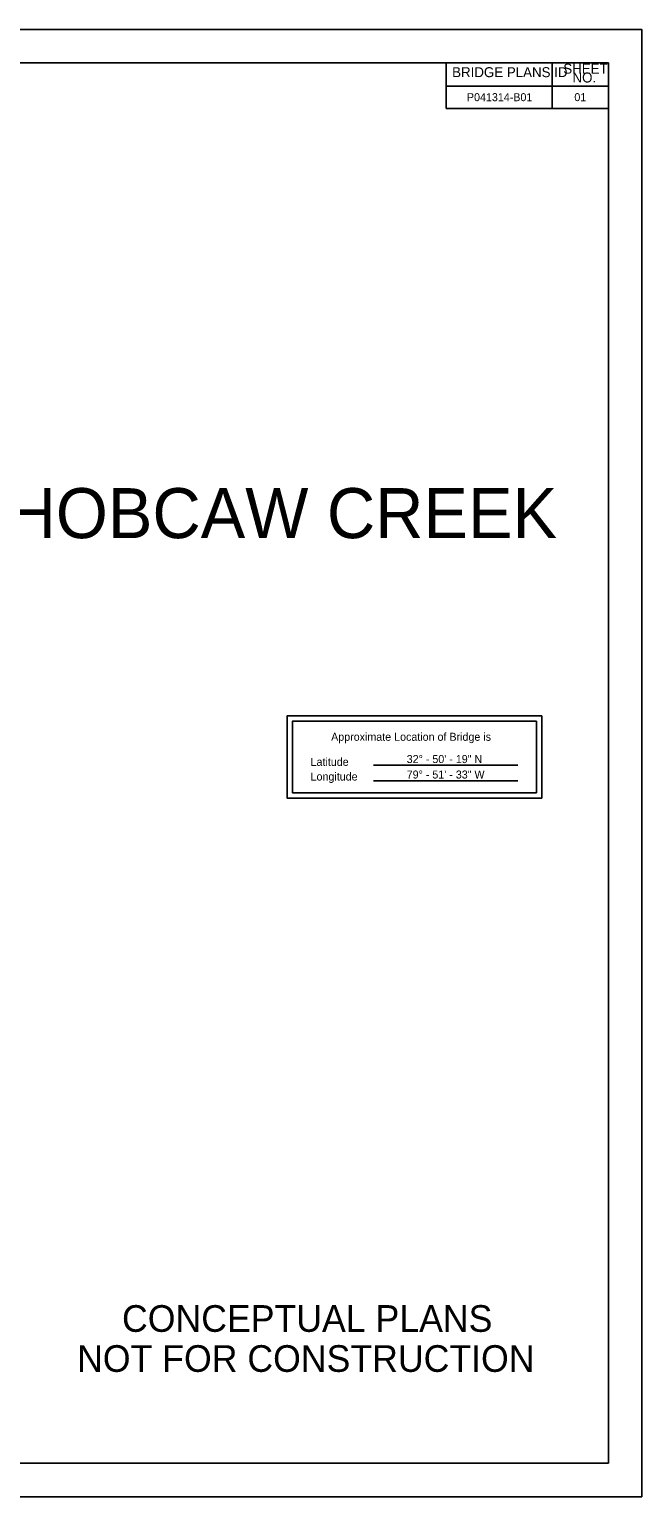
# Model space of a CAD drawing. Extents: x 291 to 2091, y 224 to 1324.
# Drawn here: x 1632 to 2091, y 224 to 1324 of the extents above; entities that cross this region are included whole.
import ezdxf

# ---------------------------------------------------------------- set-up
doc = ezdxf.new("R2010")
doc.units = 0
for name, color, linetype in [('BR_BORDER LINES', 7, 'Continuous'), ('BR_TEXT', 7, 'Continuous'), ('GN_TitleSheetMap', 7, 'Continuous'), ('RD_SHT_IplotShp', 7, 'Continuous')]:
    doc.layers.add(name, color=color, linetype=linetype)

msp = doc.modelspace()

# ---------------------------------------------------------------- linework, layer by layer
at = {"layer": 'BR_BORDER LINES'}
for p, q in [((391.1, 1299), (2066.1, 1299)), ((1944.4, 1299), (1944.4, 1264.8)), ((2023.9, 1264.8), (2023.9, 1299)), ((2066.1, 249.1), (2066.1, 1299)), ((1944.4, 1281.5), (2066.1, 1281.5)), ((2066.1, 1240.8), (2066.1, 1265.7)), ((1944.4, 1264.8), (2066.1, 1264.8)), ((2066.1, 888.4), (2066.1, 1240.8)), ((391.1, 249.1), (2066.1, 249.1))]:
    msp.add_line(p, q, dxfattribs=at)
at = {"layer": 'BR_TEXT'}
for points in [[(2016.1, 809.3), (1825, 809.3), (1825, 747.7), (2016.1, 747.7)], [(2012.1, 805.3), (1829, 805.3), (1829, 751.7), (2012.1, 751.7)]]:
    msp.add_lwpolyline(points, close=True, dxfattribs=at)
at = {"layer": 'GN_TitleSheetMap'}
for p, q in [((1890, 772.3), (1998.1, 772.3)), ((1890, 760.7), (1998.1, 760.7))]:
    msp.add_line(p, q, dxfattribs=at)
at = {"layer": 'RD_SHT_IplotShp'}
msp.add_lwpolyline([(291.1, 1324), (2091.1, 1324), (2091.1, 224), (291.1, 224)], close=True, dxfattribs=at)

# ---------------------------------------------------------------- texts
at = {"layer": 'BR_TEXT'}
for s, height, p in [('SHEET', 7.47, (2032.3, 1290.8)), ('BRIDGE PLANS ID', 7.466, (1948.9, 1288.2)), ('NO.', 7.47, (2039.2, 1284.2)), ('REPLACE BRIDGE OVER TRIBUTARY TO HOBCAW CREEK', 37.5, (623.4, 942.6)), ('Approximate Location of Bridge is', 6, (1858.1, 790.7)), ('Latitude', 6, (1842.7, 771.9)), ('32%%D - 50\' - 19" N', 6, (1914.8, 774)), ('Longitude', 6, (1842.7, 760.9)), ('79%%D - 51\' - 33" W', 6, (1914.8, 762.4)), ('CONCEPTUAL PLANS', 20, (1701.2, 347.6)), ('NOT FOR CONSTRUCTION', 20, (1667.5, 317.6))]:
    msp.add_text(s, height=height, dxfattribs=at).set_placement(p)
for s, height, p in [('P041314-B01', 5.999, (1960, 1270.2)), ('01', 6, (2040.6, 1270.2))]:
    msp.add_text(s, height=height, rotation=0.0002, dxfattribs=at).set_placement(p)

doc.saveas('drawing.dxf')
